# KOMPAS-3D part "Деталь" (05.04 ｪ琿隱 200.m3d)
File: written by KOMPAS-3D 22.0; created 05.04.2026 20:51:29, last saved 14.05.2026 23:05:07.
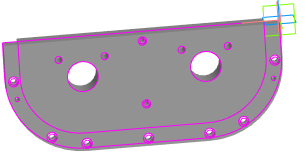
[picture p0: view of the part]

Document properties: Автор: taras; Полное имя файла: E:\test_kompas\all_v20\05.04 крышка200.m3d

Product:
- Part/product: Деталь
    Масса: 19.948382

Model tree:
1. Эскиз:3
2. Элемент выдавливания:24
     Расстояние 1 = 20
3. Элемент выдавливания:25
     Расстояние 1 = -20
4. Эскиз:4  (with: Элемент выдавливания:24)
5. Элемент выдавливания:26
     Расстояние 1 = -40
6. Элемент выдавливания:27
     Расстояние 1 = -40
7. Элемент выдавливания:28
     Расстояние 2 = 40
8. Элемент выдавливания:29
     Расстояние 2 = 11
9. Элемент выдавливания:30
     Расстояние 2 = 20
10. Элемент выдавливания:31
     Расстояние 2 = 20
11. Элемент выдавливания:32
     Расстояние 2 = 30
12. Элемент выдавливания:35
     Расстояние 2 = 20
13. Элемент выдавливания:36
     Расстояние 2 = 10
14. Элемент выдавливания:37
     Расстояние 2 = 40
